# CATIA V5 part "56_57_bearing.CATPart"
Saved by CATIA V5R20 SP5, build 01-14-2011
Part number: 56_57_bearing
Bounding box of the stored display mesh (mm): x -15.993 to 15.993, y 124.369 to 156.355, z 111 to 129
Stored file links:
  C:\Documents and Settings\anizard\Bureau\13\56_57_bearing.CATPart
  C:\Documents and Settings\anizard\Bureau\13\anizard.CATProduct
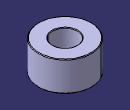
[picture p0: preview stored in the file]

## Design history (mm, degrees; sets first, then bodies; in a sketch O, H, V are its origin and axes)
Set1
  Plane1 to Plane3: linked copy from another document
  Point1: linked copy from another document
  Line1: linked copy from another document
  Point2: linked copy from another document
Body1 (main body)
  Sketch1 on Plane1, origin (0, 0, 0), H (0, 1, 0), V (0, 0, 1)
    line L1 (148.2155, 129) -> (156.0084, 129)
    line L2 (156.3619, 128.6464) -> (156.3619, 111.3536)
    line L3 (156.0084, 111) -> (148.2155, 111)
    line L4 (147.8619, 111.3536) -> (147.8619, 128.6464)
    reference intersected line E1 through (0, 111) direction (-1, 0) from Plane2
    reference intersected line E2 through (0, 129) direction (-1, 0) from Plane3
    reference projected point E3 (147.8619, 111) from Point1
    line L5 (156.3619, 111.3536) -> (156.0084, 111)
    line L6 (156.0084, 129) -> (156.3619, 128.6464)
    line L7 (148.2155, 129) -> (147.8619, 128.6464)
    line L8 (148.2155, 111) -> (147.8619, 111.3536)
    reference projected point E4 (156.3619, 132) from Point2
    angle L2 L5 = 45
    length L5 = 0.5
    angle L1 L6 = 45
    length L6 = 0.5
    angle L1 L7 = 45
    length L7 = 0.5
    angle L3 L8 = 45
    length L8 = 0.5
    horizontal: L1 H, L3 H
    vertical: L2 V, L4 V
    coincidence: E1 L3, L1 E2, L4 E3, L2 E4
  Shaft1: profile Sketch1, axis Line1, angle 360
